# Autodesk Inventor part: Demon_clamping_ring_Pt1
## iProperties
Shininess: 64.0
Length Units: 11269
Angle Units: 11279
Time Units: 11290
Mass Units: 11283
Length Display Precision: 3
Angle Display Precision: 2
Compacted: True
Part Number: Demon_clamping_ring_Pt1
Document SubType Name: Modeling
Created: 2005-04
Designer: John Blackburn
Manufacturer: Standard
Standards Organization: Custom
Density: 0.0
Volumn: 0.0
Area: 0.0
PropertySet Name: Model Information
Control State: 0
Master: False
Checked Out: False
Author: John Blackburn
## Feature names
1. Extrusion1
2. Extrusion3
